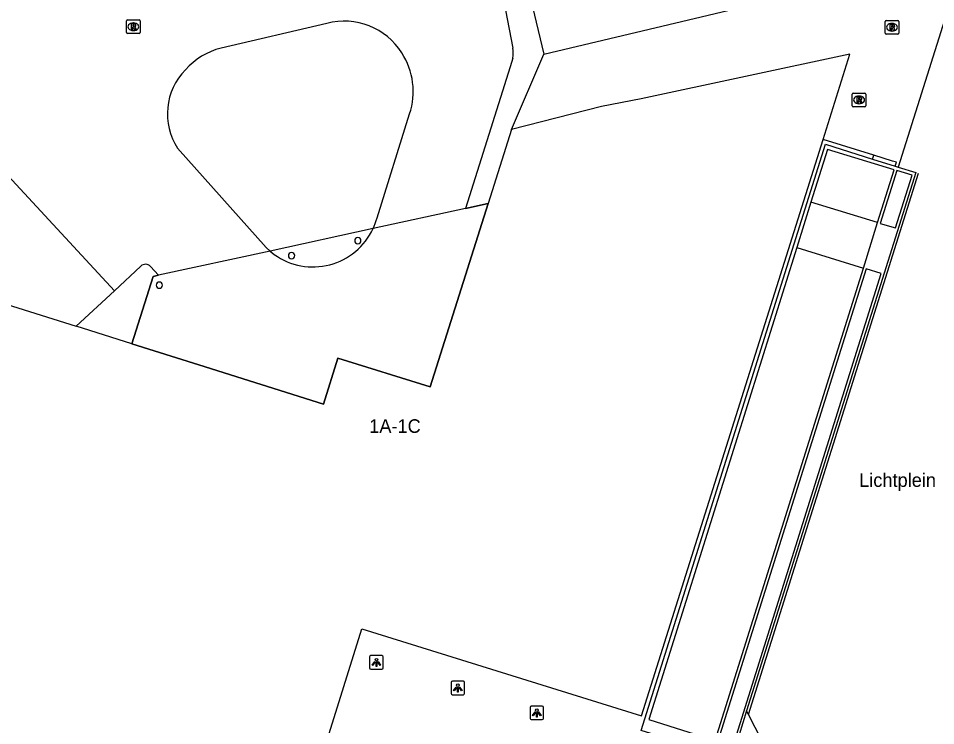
# Model space of a CAD drawing. Extents: x 160676 to 161153, y 383244 to 383713.
# Drawn here: x 160986.7 to 161054.2, y 383384.8 to 383436.8 of the extents above; entities that cross this region are included whole.
import ezdxf

# ---------------------------------------------------------------- set-up
doc = ezdxf.new("R2010")
doc.units = 0
for name, color, linetype in [('IMGEO_Hek', 7, 'Continuous'), ('IMGEO_Lichtpunt', 7, 'Continuous'), ('IMGEO_Lijnafwatering', 7, 'Continuous'), ('IMGEO_Muur', 7, 'Continuous'), ('IMGEO_Openbare_ruimte_label', 7, 'Continuous'), ('IMGEO_Pand', 7, 'Continuous'), ('IMGEO_Pand_nummerreeks', 7, 'Continuous'), ('IMGEO_Pand_overbouw', 7, 'Continuous'), ('IMGEO_Rijbaan_lokaal_open', 7, 'Continuous'), ('IMGEO_Rioolput', 7, 'Continuous'), ('IMGEO_Voetpad_open', 7, 'Continuous')]:
    doc.layers.add(name, color=color, linetype=linetype)

msp = doc.modelspace()

# ---------------------------------------------------------------- linework, layer by layer
at = {"layer": 'IMGEO_Hek'}
msp.add_lwpolyline([(161049.64, 383426.719), (161045.909, 383427.885)], dxfattribs=at)
at = {"layer": 'IMGEO_Lichtpunt'}
for p, q in [((161012.551, 383389.845), (161012.551, 383389.038)), ((161012.551, 383389.845), (161012.551, 383389.038)), ((161013.453, 383389.94), (161012.645, 383389.94)), ((161013.453, 383389.94), (161012.645, 383389.94)), ((161013.547, 383389.038), (161013.547, 383389.845)), ((161013.547, 383389.038), (161013.547, 383389.845)), ((161012.645, 383388.944), (161013.453, 383388.944)), ((161012.645, 383388.944), (161013.453, 383388.944)), ((161018.546, 383387.971), (161018.546, 383387.164)), ((161018.546, 383387.971), (161018.546, 383387.164)), ((161019.448, 383388.066), (161018.64, 383388.066)), ((161019.448, 383388.066), (161018.64, 383388.066)), ((161019.542, 383387.164), (161019.542, 383387.971)), ((161019.542, 383387.164), (161019.542, 383387.971)), ((161018.64, 383387.07), (161019.448, 383387.07)), ((161018.64, 383387.07), (161019.448, 383387.07)), ((161024.35, 383386.136), (161024.35, 383385.329)), ((161024.35, 383386.136), (161024.35, 383385.329)), ((161025.252, 383386.231), (161024.444, 383386.231)), ((161025.252, 383386.231), (161024.444, 383386.231)), ((161025.346, 383385.329), (161025.346, 383386.136)), ((161025.346, 383385.329), (161025.346, 383386.136)), ((161024.444, 383385.235), (161025.252, 383385.235)), ((161024.444, 383385.235), (161025.252, 383385.235))]:
    msp.add_line(p, q, dxfattribs=at)
for points in [[(161012.925, 383389.509), (161012.964, 383389.481), (161012.776, 383389.219), (161012.738, 383389.246), (161012.925, 383389.509)], [(161013.027, 383389.461), (161013.074, 383389.461), (161013.074, 383389.139), (161013.027, 383389.139), (161013.027, 383389.461)], [(161013.137, 383389.481), (161013.175, 383389.508), (161013.362, 383389.246), (161013.323, 383389.218), (161013.137, 383389.481)], [(161018.92, 383387.635), (161018.959, 383387.607), (161018.771, 383387.345), (161018.733, 383387.372), (161018.92, 383387.635)], [(161019.132, 383387.607), (161019.17, 383387.634), (161019.357, 383387.372), (161019.318, 383387.344), (161019.132, 383387.607)], [(161019.022, 383387.587), (161019.069, 383387.587), (161019.069, 383387.265), (161019.022, 383387.265), (161019.022, 383387.587)], [(161024.724, 383385.8), (161024.763, 383385.772), (161024.575, 383385.51), (161024.537, 383385.537), (161024.724, 383385.8)], [(161024.826, 383385.752), (161024.873, 383385.752), (161024.873, 383385.43), (161024.826, 383385.43), (161024.826, 383385.752)], [(161024.936, 383385.772), (161024.974, 383385.799), (161025.161, 383385.537), (161025.122, 383385.509), (161024.936, 383385.772)]]:
    msp.add_lwpolyline(points, dxfattribs=at)
for centre in [(161013.05, 383389.643), (161019.045, 383387.769), (161024.849, 383385.934)]:
    msp.add_circle(centre, 0.0994, dxfattribs=at)
for centre, start, end in [((161012.645, 383389.845), 90, 180), ((161012.645, 383389.845), 90, 180), ((161013.453, 383389.845), 0, 90), ((161013.453, 383389.845), 0, 90), ((161012.645, 383389.038), 180, 270), ((161012.645, 383389.038), 180, 270), ((161013.453, 383389.038), 270, 0), ((161013.453, 383389.038), 270, 360), ((161018.64, 383387.971), 90, 180), ((161018.64, 383387.971), 90, 180), ((161019.448, 383387.971), 0, 90), ((161019.448, 383387.971), 0, 90), ((161018.64, 383387.164), 180, 270), ((161018.64, 383387.164), 180, 270), ((161019.448, 383387.164), 270, 0), ((161019.448, 383387.164), 270, 360), ((161024.444, 383386.136), 90, 180), ((161024.444, 383386.136), 90, 180), ((161025.252, 383386.136), 0, 90), ((161025.252, 383386.136), 0, 90), ((161024.444, 383385.329), 180, 270), ((161024.444, 383385.329), 180, 270), ((161025.252, 383385.329), 270, 0), ((161025.252, 383385.329), 270, 360)]:
    msp.add_arc(centre, 0.0946, start, end, dxfattribs=at)
at = {"layer": 'IMGEO_Lijnafwatering'}
for points in [[(161059.617, 383435.13), (161054.833, 383436.641), (161051.429, 383425.846)], [(161046.662, 383405.512), (161048.746, 383412.14), (161052.914, 383425.398)], [(161040.41, 383385.625), (161044.578, 383398.883), (161046.662, 383405.512)]]:
    msp.add_lwpolyline(points, dxfattribs=at)
at = {"layer": 'IMGEO_Muur'}
for points in [[(161040.28, 383385.878), (161039.196, 383382.354), (161035.432, 383383.524), (161032.515, 383384.431), (161046.083, 383427.531), (161049.551, 383426.438)], [(161048.883, 383418.423), (161049.92, 383421.775), (161051.143, 383425.655), (161046.236, 383427.152), (161045.017, 383423.27), (161043.97, 383419.933), (161033.081, 383385.244), (161037.97, 383383.715), (161048.883, 383418.423)], [(161051.214, 383425.911), (161051.429, 383425.846), (161052.723, 383425.456), (161040.28, 383385.878)], [(161051.233, 383421.375), (161052.451, 383425.256), (161051.334, 383425.597), (161050.111, 383421.717), (161051.233, 383421.375)], [(161039.284, 383383.304), (161050.181, 383418.024), (161049.074, 383418.364), (161038.161, 383383.655), (161039.284, 383383.304)]]:
    msp.add_lwpolyline(points, dxfattribs=at)
at = {"layer": 'IMGEO_Pand'}
for points in [[(161013.154, 383515.953), (161015.091, 383507.815), (161016.531, 383508.157), (161018.313, 383500.667), (161015.35, 383499.959), (161015.25, 383500.388), (161010.2, 383499.211), (161011.421, 383494.179), (161011.858, 383494.285), (161014.465, 383483.45), (161014.985, 383481.288), (161022.819, 383448.908), (161021.892, 383448.714), (161025.358, 383434.141)], [(161025.358, 383434.141), (161049.535, 383439.901)], [(161045.909, 383427.885), (161047.883, 383434.148), (161032.528, 383430.873), (161029.611, 383430.31), (161022.993, 383428.609)], [(161022.993, 383428.609), (161021.266, 383423.165)], [(161009.323, 383383.438), (161011.968, 383391.902), (161032.552, 383385.506), (161045.909, 383427.885)], [(161049.551, 383426.438), (161049.64, 383426.719)], [(161049.551, 383426.438), (161051.214, 383425.911)], [(161051.214, 383425.911), (161051.306, 383426.202), (161051.018, 383426.293), (161049.64, 383426.719)], [(161021.266, 383423.165), (161016.995, 383409.701), (161010.218, 383411.816), (161009.156, 383408.436), (161000, 383411.313), (160995.072, 383412.862)], [(160964.397, 383410.461), (160967.849, 383421.416), (160990.957, 383414.155)], [(160995.072, 383412.862), (160990.957, 383414.155)]]:
    msp.add_lwpolyline(points, dxfattribs=at)
for centre, start, end in [((161011.688, 383420.44), 90, 270), ((161011.688, 383420.44), 270, 90), ((161006.81, 383419.349), 90, 270), ((161006.81, 383419.349), 270, 90), ((160997.079, 383417.175), 90, 270), ((160997.079, 383417.175), 270, 90)]:
    msp.add_arc(centre, 0.23, start, end, dxfattribs=at)
at = {"layer": 'IMGEO_Pand_overbouw'}
msp.add_lwpolyline([(161021.266, 383423.165), (161019.614, 383422.806), (161012.809, 383421.326), (161005.24, 383419.681), (160997.029, 383417.896), (160996.626, 383417.808), (160995.072, 383412.862), (161000, 383411.313), (161009.156, 383408.436), (161010.218, 383411.816), (161016.995, 383409.701)], close=True, dxfattribs=at)
at = {"layer": 'IMGEO_Rijbaan_lokaal_open'}
for points in [[(161020.237, 383449.35), (161023.095, 383434.591)], [(161009.411, 383436.408), (161001.625, 383434.6)], [(161023.089, 383433.867), (161022.883, 383433.221), (161019.614, 383422.806), (161021.266, 383423.165)], [(160993.778, 383416.768), (160985.645, 383425.552), (160984.098, 383431.98), (160983.287, 383431.735)], [(161013.101, 383422.12), (161015.496, 383429.76)], [(160998.419, 383427.231), (161004.949, 383419.934), (161005.24, 383419.681), (161005.542, 383419.419)], [(160995.733, 383418.579), (160993.778, 383416.768)], [(160995.072, 383412.862), (160996.626, 383417.808), (160997.029, 383417.896), (160996.431, 383418.549)]]:
    msp.add_lwpolyline(points, dxfattribs=at)
for centre, radius, start, end in [((161010.698, 383431.58), 4.996, 32.21624, 104.92816), ((161003.026, 383429.318), 5.464, 104.85359, 137.47096), ((161010.491, 383431.401), 5.267, 341.8475, 32.66666), ((161020.679, 383434.249), 2.44, 350.99468, 8.05569), ((161002.354, 383429.756), 4.676, 135.85773, 212.6838), ((161008.306, 383423.433), 4.972, 334.92815, 344.68903), ((161008.378, 383423.41), 4.896, 234.60029, 334.80765), ((160996.067, 383418.216), 0.493, 42.41861, 132.65928)]:
    msp.add_arc(centre, radius, start, end, dxfattribs=at)
at = {"layer": 'IMGEO_Rioolput'}
for p, q in [((160994.669, 383435.744), (160994.669, 383436.596)), ((160994.744, 383436.67), (160995.596, 383436.67)), ((160995.157, 383436.45), (160995.182, 383436.45)), ((160995.67, 383436.596), (160995.67, 383435.744)), ((161050.477, 383435.702), (161050.477, 383436.554)), ((161050.552, 383436.628), (161051.404, 383436.628)), ((161050.965, 383436.408), (161050.99, 383436.408)), ((161051.478, 383436.554), (161051.478, 383435.702)), ((160995.596, 383435.67), (160994.744, 383435.67)), ((160995.18, 383435.89), (160995.155, 383435.89)), ((161051.404, 383435.628), (161050.552, 383435.628)), ((161050.988, 383435.848), (161050.963, 383435.848)), ((161048.054, 383430.365), (161048.054, 383431.217)), ((161048.129, 383431.291), (161048.981, 383431.291)), ((161048.542, 383431.071), (161048.567, 383431.071)), ((161049.055, 383431.217), (161049.055, 383430.365)), ((161048.981, 383430.291), (161048.129, 383430.291)), ((161048.565, 383430.511), (161048.54, 383430.511))]:
    msp.add_line(p, q, dxfattribs=at)
for points in [[(160994.669, 383435.744), (160994.669, 383436.596)], [(160994.744, 383436.67), (160995.596, 383436.67)], [(160995.258, 383436.368), (160995.006, 383436.37), (160995.006, 383435.97)], [(160995.184, 383436.289), (160995.13, 383436.289), (160995.13, 383436.208)], [(160995.13, 383436.208), (160995.182, 383436.208)], [(160995.67, 383436.596), (160995.67, 383435.744)], [(161050.477, 383435.702), (161050.477, 383436.554)], [(161050.552, 383436.628), (161051.404, 383436.628)], [(161051.066, 383436.326), (161050.814, 383436.328), (161050.814, 383435.928)], [(161050.992, 383436.247), (161050.938, 383436.247), (161050.938, 383436.166)], [(161051.478, 383436.554), (161051.478, 383435.702)], [(160995.596, 383435.67), (160994.744, 383435.67)], [(160995.006, 383435.97), (160995.13, 383435.97), (160995.13, 383436.132), (160995.141, 383436.132)], [(160995.188, 383436.103), (160995.259, 383435.97), (160995.399, 383435.97), (160995.334, 383436.096)], [(161051.404, 383435.628), (161050.552, 383435.628)], [(161050.814, 383435.928), (161050.938, 383435.928), (161050.938, 383436.09), (161050.949, 383436.09)], [(161050.938, 383436.166), (161050.99, 383436.166)], [(161050.996, 383436.061), (161051.067, 383435.928), (161051.207, 383435.928), (161051.142, 383436.054)], [(161048.054, 383430.365), (161048.054, 383431.217)], [(161048.129, 383431.291), (161048.981, 383431.291)], [(161048.643, 383430.989), (161048.391, 383430.991), (161048.391, 383430.591)], [(161048.569, 383430.91), (161048.515, 383430.91), (161048.515, 383430.829)], [(161048.515, 383430.829), (161048.567, 383430.829)], [(161049.055, 383431.217), (161049.055, 383430.365)], [(161048.981, 383430.291), (161048.129, 383430.291)], [(161048.391, 383430.591), (161048.515, 383430.591), (161048.515, 383430.753), (161048.526, 383430.753)], [(161048.573, 383430.724), (161048.644, 383430.591), (161048.784, 383430.591), (161048.719, 383430.717)]]:
    msp.add_lwpolyline(points, dxfattribs=at)
for centre, radius, start, end in [((160994.746, 383436.594), 0.0765, 91.55205, 178.44795), ((160994.746, 383436.594), 0.0765, 91.55205, 178.44795), ((160995.166, 383436.397), 0.19, 274.7715, 282.96867), ((160995.19, 383436.193), 0.0964, 77.00612, 93.18647), ((160995.204, 383436.25), 0.0378, 276.66336, 79.67722), ((160995.257, 383436.258), 0.109, 350.36119, 89.41601), ((160995.255, 383436.258), 0.112, 277.58423, 350.98172), ((160995.594, 383436.594), 0.0765, 1.55205, 88.44795), ((160995.594, 383436.594), 0.0765, 1.55205, 88.44795), ((161050.554, 383436.552), 0.0765, 91.55205, 178.44795), ((161050.554, 383436.552), 0.0765, 91.55205, 178.44795), ((161050.998, 383436.151), 0.0964, 77.00612, 93.18647), ((161051.012, 383436.208), 0.0378, 276.66336, 79.67722), ((161051.065, 383436.216), 0.109, 350.36119, 89.41601), ((161051.063, 383436.216), 0.112, 277.58423, 350.98172), ((161051.402, 383436.552), 0.0765, 1.55205, 88.44795), ((161051.402, 383436.552), 0.0765, 1.55205, 88.44795), ((160994.746, 383435.746), 0.0765, 181.55205, 268.44795), ((160994.746, 383435.746), 0.0765, 181.55205, 268.44795), ((160995.14, 383436.079), 0.0533, 26.02933, 88.69889), ((160995.239, 383436.043), 0.108, 29.51342, 73.79051), ((160995.594, 383435.746), 0.0765, 271.55205, 358.44795), ((160995.594, 383435.746), 0.0765, 271.55205, 358.44795), ((161050.554, 383435.704), 0.0765, 181.55205, 268.44795), ((161050.554, 383435.704), 0.0765, 181.55205, 268.44795), ((161050.948, 383436.037), 0.0533, 26.02933, 88.69889), ((161050.974, 383436.355), 0.19, 274.7715, 282.96867), ((161051.047, 383436.001), 0.108, 29.51342, 73.79051), ((161051.402, 383435.704), 0.0765, 271.55205, 358.44795), ((161051.402, 383435.704), 0.0765, 271.55205, 358.44795), ((161048.131, 383431.215), 0.0765, 91.55205, 178.44795), ((161048.131, 383431.215), 0.0765, 91.55205, 178.44795), ((161048.551, 383431.018), 0.19, 274.7715, 282.96867), ((161048.575, 383430.814), 0.0964, 77.00612, 93.18647), ((161048.589, 383430.871), 0.0378, 276.66336, 79.67722), ((161048.642, 383430.879), 0.109, 350.36119, 89.41601), ((161048.64, 383430.879), 0.112, 277.58423, 350.98172), ((161048.979, 383431.215), 0.0765, 1.55205, 88.44795), ((161048.979, 383431.215), 0.0765, 1.55205, 88.44795), ((161048.131, 383430.367), 0.0765, 181.55205, 268.44795), ((161048.131, 383430.367), 0.0765, 181.55205, 268.44795), ((161048.525, 383430.7), 0.0533, 26.02933, 88.69889), ((161048.624, 383430.664), 0.108, 29.51342, 73.79051), ((161048.979, 383430.367), 0.0765, 271.55205, 358.44795), ((161048.979, 383430.367), 0.0765, 271.55205, 358.44795)]:
    msp.add_arc(centre, radius, start, end, dxfattribs=at)
for centre, major_axis, ratio, start_param, end_param in [((160995.156, 383436.17), (-0.387, 0.002), 0.722429, 4.712389, 7.853982), ((160995.181, 383436.17), (-0.39, 0.002), 0.717154, 1.570796, 4.712389), ((161050.964, 383436.128), (-0.387, 0.002), 0.722429, 4.712389, 7.853982), ((161050.989, 383436.128), (-0.39, 0.002), 0.717154, 1.570796, 4.712389), ((161048.541, 383430.791), (-0.387, 0.002), 0.722429, 4.712389, 7.853982), ((161048.566, 383430.791), (-0.39, 0.002), 0.717154, 1.570796, 4.712389)]:
    msp.add_ellipse(centre, major_axis=major_axis, ratio=ratio, start_param=start_param, end_param=end_param, dxfattribs=at)
at = {"layer": 'IMGEO_Voetpad_open'}
for points in [[(161022.993, 383428.609), (161025.358, 383434.141)], [(161049.64, 383426.719), (161045.909, 383427.885)], [(161049.92, 383421.775), (161045.017, 383423.27), (161043.97, 383419.933), (161048.883, 383418.423), (161049.92, 383421.775)], [(161072.736, 383422.509), (161061.981, 383388.875), (161061.791, 383388.956), (161060.03, 383388.472), (161051.68, 383376.521), (161048.527, 383377.888), (161047.628, 383382.235), (161042.897, 383380.639), (161042.849, 383380.891), (161040.41, 383385.625), (161040.28, 383385.878)], [(160990.957, 383414.155), (160993.778, 383416.768)]]:
    msp.add_lwpolyline(points, dxfattribs=at)

# ---------------------------------------------------------------- texts
at = {"layer": 'IMGEO_Openbare_ruimte_label'}
msp.add_text('Lichtplein', height=1, dxfattribs=at).set_placement((161048.56, 383402.344))
at = {"layer": 'IMGEO_Pand_nummerreeks'}
msp.add_text('1A-1C', height=1, dxfattribs=at).set_placement((161012.523, 383406.315))

doc.saveas('drawing.dxf')
